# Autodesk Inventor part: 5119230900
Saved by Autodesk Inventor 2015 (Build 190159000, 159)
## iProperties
Created: 2020-07
Part Number: 5119230900
Checked By: TraceParts S.A.
Material: Generic
Catalog Web Link: www.traceparts.com
Document SubType Name: Modeling
Designer: TraceParts
Density: 1 g/cm^3
Appearance: Default
Company: TraceParts S.A.
Author: TraceParts
REFERENCE: 5119230900
DESIGN: HIT-1250 P 0,75KW (230/400V 50HZ) - 5119230900
SUPPLIER: Soler & Palau
TraceParts.PartNumber: 10-20122018-119595
TraceParts.PartTitle: HIB-P/HIT-P
TraceParts.InstanceId: 10-20122018-119595A2I5DVU8EXDEFA5JXCNR2KED0
TraceParts.PartStatus: Published
TraceParts.PartVersion: 1.0.2
TRACEPARTS: TRACEPARTS
TraceParts.PartLanguage: en
TraceParts.ClassPath: SOLER_PALAU:10-20122018-119595
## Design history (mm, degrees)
feature "5119230900"
body "Solid1"
